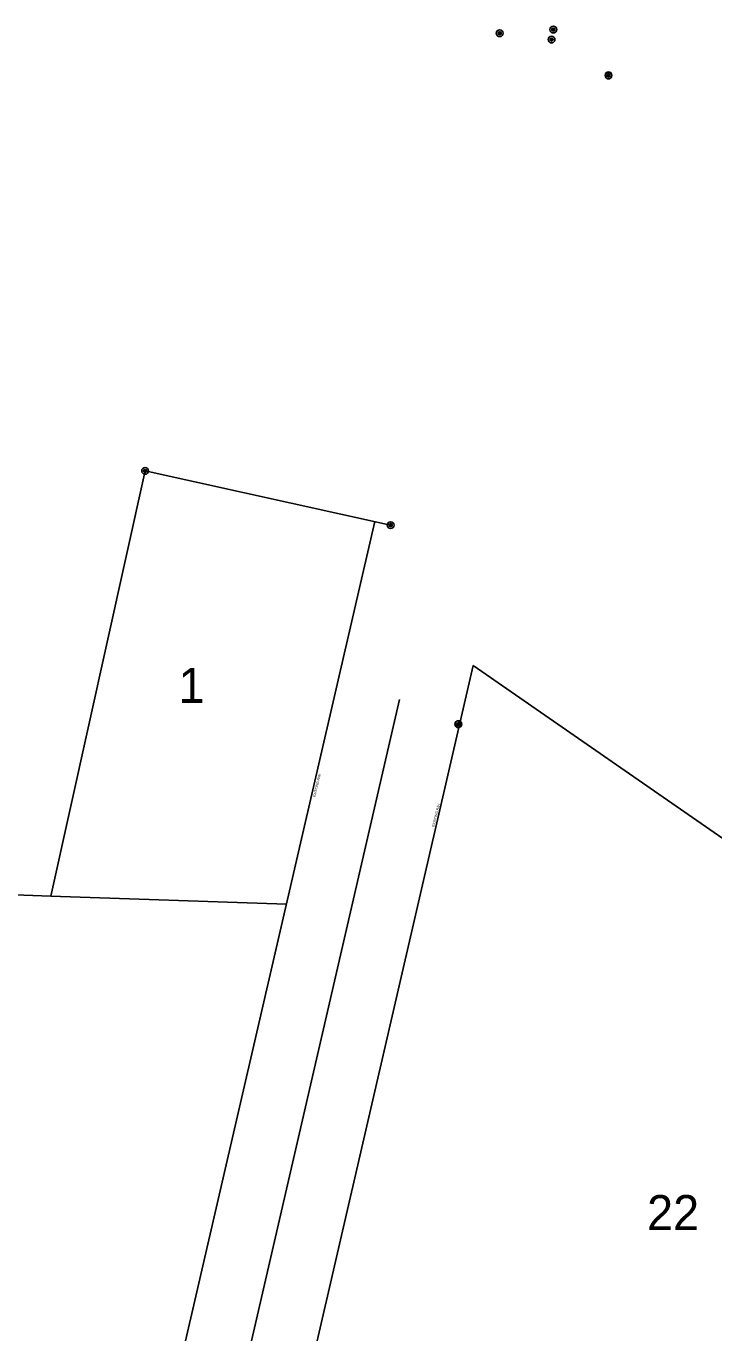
# Model space of a CAD drawing. Extents: x 1398271 to 1401121, y 1018936 to 1022764.
# Drawn here: x 1400414 to 1400768, y 1022077 to 1022749 of the extents above; entities that cross this region are included whole.
import ezdxf

# ---------------------------------------------------------------- set-up
doc = ezdxf.new("R2010")
doc.units = 0
for name, color, linetype in [('RD_EX_DV_Prop', 7, 'Continuous'), ('RD_EX_DV_PropPin', 7, 'Continuous'), ('RD_EX_DV_TX_Prop', 7, 'Continuous'), ('RD_EX_RW', 7, 'Continuous'), ('RD_EX_RW_TX', 7, 'Continuous'), ('RD_HC_Cl', 7, 'Continuous'), ('RD_SMD_Locator', 7, 'Continuous')]:
    doc.layers.add(name, color=color, linetype=linetype)

msp = doc.modelspace()

# ---------------------------------------------------------------- linework, layer by layer
at = {"layer": 'RD_EX_DV_Prop'}
for p, q in [((1400426.75, 1022301.66), (1400475.22, 1022520.32)), ((1400475.22, 1022520.32), (1400601.41, 1022492.39)), ((1400643.96, 1022420.21), (1400900.12, 1022242.43)), ((1400426.75, 1022301.66), (1400308.27, 1022305.78)), ((1400547.84, 1022297.44), (1400426.75, 1022301.66))]:
    msp.add_line(p, q, dxfattribs=at)
at = {"layer": 'RD_EX_DV_PropPin'}
for p, q in [((1400656.79, 1022745.08), (1400656.79, 1022745.47)), ((1400656.83, 1022744.97), (1400656.83, 1022745.57)), ((1400656.86, 1022744.9), (1400656.86, 1022745.64)), ((1400656.9, 1022744.85), (1400656.9, 1022745.7)), ((1400656.93, 1022744.8), (1400656.93, 1022745.75)), ((1400656.97, 1022744.76), (1400656.97, 1022745.79)), ((1400657, 1022744.72), (1400657, 1022745.82)), ((1400657.04, 1022744.69), (1400657.04, 1022745.85)), ((1400657.07, 1022744.66), (1400657.07, 1022745.88)), ((1400657.11, 1022744.64), (1400657.11, 1022745.91)), ((1400657.14, 1022744.62), (1400657.14, 1022745.93)), ((1400657.18, 1022744.6), (1400657.18, 1022745.95)), ((1400657.21, 1022744.58), (1400657.21, 1022745.97)), ((1400657.25, 1022744.56), (1400657.25, 1022745.98)), ((1400657.28, 1022744.55), (1400657.28, 1022745.99)), ((1400657.32, 1022744.54), (1400657.32, 1022746)), ((1400657.35, 1022744.53), (1400657.35, 1022746.01)), ((1400657.39, 1022744.52), (1400657.39, 1022746.02)), ((1400657.42, 1022744.52), (1400657.42, 1022746.03)), ((1400657.46, 1022744.51), (1400657.46, 1022746.03)), ((1400657.49, 1022744.51), (1400657.49, 1022746.03)), ((1400657.53, 1022744.51), (1400657.53, 1022746.03)), ((1400657.56, 1022744.51), (1400657.56, 1022746.03)), ((1400657.6, 1022744.51), (1400657.6, 1022746.03)), ((1400657.63, 1022744.52), (1400657.63, 1022746.03)), ((1400657.67, 1022744.52), (1400657.67, 1022746.02)), ((1400657.7, 1022744.53), (1400657.7, 1022746.01)), ((1400657.74, 1022744.54), (1400657.74, 1022746)), ((1400657.77, 1022744.55), (1400657.77, 1022745.99)), ((1400657.81, 1022744.56), (1400657.81, 1022745.98)), ((1400657.84, 1022744.58), (1400657.84, 1022745.97)), ((1400657.88, 1022744.6), (1400657.88, 1022745.95)), ((1400657.91, 1022744.62), (1400657.91, 1022745.93)), ((1400657.95, 1022744.64), (1400657.95, 1022745.91)), ((1400657.98, 1022744.66), (1400657.98, 1022745.88)), ((1400658.02, 1022744.69), (1400658.02, 1022745.85)), ((1400658.05, 1022744.72), (1400658.05, 1022745.82)), ((1400658.09, 1022744.76), (1400658.09, 1022745.79)), ((1400658.12, 1022744.8), (1400658.12, 1022745.75)), ((1400658.16, 1022744.85), (1400658.16, 1022745.7)), ((1400658.19, 1022744.9), (1400658.19, 1022745.64)), ((1400658.23, 1022744.97), (1400658.23, 1022745.57)), ((1400658.26, 1022745.08), (1400658.26, 1022745.47)), ((1400683.46, 1022741.82), (1400683.46, 1022742.21)), ((1400683.49, 1022741.72), (1400683.49, 1022742.31)), ((1400683.53, 1022741.64), (1400683.53, 1022742.38)), ((1400683.56, 1022741.59), (1400683.56, 1022742.44)), ((1400683.6, 1022741.54), (1400683.6, 1022742.49)), ((1400683.63, 1022741.5), (1400683.63, 1022742.53)), ((1400683.67, 1022741.46), (1400683.67, 1022742.56)), ((1400683.7, 1022741.43), (1400683.7, 1022742.6)), ((1400683.74, 1022741.4), (1400683.74, 1022742.62)), ((1400683.77, 1022741.38), (1400683.77, 1022742.65)), ((1400683.81, 1022741.36), (1400683.81, 1022742.67)), ((1400683.84, 1022741.34), (1400683.84, 1022742.69)), ((1400683.88, 1022741.32), (1400683.88, 1022742.71)), ((1400683.91, 1022741.31), (1400683.91, 1022742.72)), ((1400683.95, 1022741.29), (1400683.95, 1022742.73)), ((1400683.98, 1022741.28), (1400683.98, 1022742.74)), ((1400684.02, 1022741.27), (1400684.02, 1022742.75)), ((1400684.05, 1022741.27), (1400684.05, 1022742.76)), ((1400684.09, 1022741.26), (1400684.09, 1022742.77)), ((1400684.12, 1022741.26), (1400684.12, 1022742.77)), ((1400684.16, 1022741.25), (1400684.16, 1022742.77)), ((1400684.19, 1022741.25), (1400684.19, 1022742.77)), ((1400684.23, 1022741.25), (1400684.23, 1022742.77)), ((1400684.26, 1022741.26), (1400684.26, 1022742.77)), ((1400684.3, 1022741.26), (1400684.3, 1022742.77)), ((1400684.33, 1022741.27), (1400684.33, 1022742.76)), ((1400684.36, 1022746.98), (1400684.36, 1022747.37)), ((1400684.37, 1022741.27), (1400684.37, 1022742.75)), ((1400684.39, 1022746.87), (1400684.39, 1022747.47)), ((1400684.4, 1022741.28), (1400684.4, 1022742.74)), ((1400684.43, 1022746.8), (1400684.43, 1022747.54)), ((1400684.44, 1022741.29), (1400684.44, 1022742.73)), ((1400684.46, 1022746.74), (1400684.46, 1022747.6)), ((1400684.47, 1022741.31), (1400684.47, 1022742.72)), ((1400684.5, 1022746.7), (1400684.5, 1022747.65)), ((1400684.51, 1022741.32), (1400684.51, 1022742.71)), ((1400684.53, 1022746.66), (1400684.53, 1022747.69)), ((1400684.54, 1022741.34), (1400684.54, 1022742.69)), ((1400684.57, 1022746.62), (1400684.57, 1022747.72)), ((1400684.58, 1022741.36), (1400684.58, 1022742.67)), ((1400684.6, 1022746.59), (1400684.6, 1022747.75)), ((1400684.61, 1022741.38), (1400684.61, 1022742.65)), ((1400684.64, 1022746.56), (1400684.64, 1022747.78)), ((1400684.65, 1022741.4), (1400684.65, 1022742.62)), ((1400684.67, 1022746.54), (1400684.67, 1022747.81)), ((1400684.68, 1022741.43), (1400684.68, 1022742.6)), ((1400684.71, 1022746.52), (1400684.71, 1022747.83)), ((1400684.72, 1022741.46), (1400684.72, 1022742.56)), ((1400684.74, 1022746.5), (1400684.74, 1022747.85)), ((1400684.75, 1022741.5), (1400684.75, 1022742.53)), ((1400684.78, 1022746.48), (1400684.78, 1022747.86)), ((1400684.79, 1022741.54), (1400684.79, 1022742.49)), ((1400684.81, 1022746.46), (1400684.81, 1022747.88)), ((1400684.82, 1022741.59), (1400684.82, 1022742.44)), ((1400684.85, 1022746.45), (1400684.85, 1022747.89)), ((1400684.86, 1022741.64), (1400684.86, 1022742.38)), ((1400684.88, 1022746.44), (1400684.88, 1022747.9)), ((1400684.89, 1022741.72), (1400684.89, 1022742.31)), ((1400684.92, 1022746.43), (1400684.92, 1022747.91)), ((1400684.93, 1022741.82), (1400684.93, 1022742.21)), ((1400684.95, 1022746.42), (1400684.95, 1022747.92)), ((1400684.99, 1022746.42), (1400684.99, 1022747.93)), ((1400685.02, 1022746.41), (1400685.02, 1022747.93)), ((1400685.06, 1022746.41), (1400685.06, 1022747.93)), ((1400685.09, 1022746.41), (1400685.09, 1022747.93)), ((1400685.13, 1022746.41), (1400685.13, 1022747.93)), ((1400685.16, 1022746.41), (1400685.16, 1022747.93)), ((1400685.2, 1022746.42), (1400685.2, 1022747.93)), ((1400685.23, 1022746.42), (1400685.23, 1022747.92)), ((1400685.27, 1022746.43), (1400685.27, 1022747.91)), ((1400685.3, 1022746.44), (1400685.3, 1022747.9)), ((1400685.34, 1022746.45), (1400685.34, 1022747.89)), ((1400685.37, 1022746.46), (1400685.37, 1022747.88)), ((1400685.41, 1022746.48), (1400685.41, 1022747.86)), ((1400685.44, 1022746.5), (1400685.44, 1022747.85)), ((1400685.48, 1022746.52), (1400685.48, 1022747.83)), ((1400685.51, 1022746.54), (1400685.51, 1022747.81)), ((1400685.55, 1022746.56), (1400685.55, 1022747.78)), ((1400685.58, 1022746.59), (1400685.58, 1022747.75)), ((1400685.62, 1022746.62), (1400685.62, 1022747.72)), ((1400685.65, 1022746.66), (1400685.65, 1022747.69)), ((1400685.69, 1022746.7), (1400685.69, 1022747.65)), ((1400685.72, 1022746.74), (1400685.72, 1022747.6)), ((1400685.76, 1022746.8), (1400685.76, 1022747.54)), ((1400685.79, 1022746.87), (1400685.79, 1022747.47)), ((1400685.83, 1022746.98), (1400685.83, 1022747.37)), ((1400712.71, 1022723.31), (1400712.71, 1022723.7)), ((1400712.73, 1022723.45), (1400712.73, 1022723.85)), ((1400712.75, 1022723.21), (1400712.75, 1022723.8)), ((1400712.77, 1022723.35), (1400712.77, 1022723.95)), ((1400712.78, 1022723.14), (1400712.78, 1022723.88)), ((1400712.8, 1022723.28), (1400712.8, 1022724.02)), ((1400712.82, 1022723.08), (1400712.82, 1022723.93)), ((1400712.84, 1022723.22), (1400712.84, 1022724.08)), ((1400712.85, 1022723.03), (1400712.85, 1022723.98)), ((1400712.87, 1022723.18), (1400712.87, 1022724.12)), ((1400712.89, 1022722.99), (1400712.89, 1022724.02)), ((1400712.91, 1022723.13), (1400712.91, 1022724.16)), ((1400712.92, 1022722.96), (1400712.92, 1022724.06)), ((1400712.94, 1022723.1), (1400712.94, 1022724.2)), ((1400712.96, 1022722.92), (1400712.96, 1022724.09)), ((1400712.98, 1022723.07), (1400712.98, 1022724.23)), ((1400712.99, 1022722.9), (1400712.99, 1022724.12)), ((1400713.01, 1022723.04), (1400713.01, 1022724.26)), ((1400713.03, 1022722.87), (1400713.03, 1022724.14)), ((1400713.05, 1022723.02), (1400713.05, 1022724.28)), ((1400713.06, 1022722.85), (1400713.06, 1022724.16)), ((1400713.08, 1022722.99), (1400713.08, 1022724.31)), ((1400713.1, 1022722.83), (1400713.1, 1022724.18)), ((1400713.12, 1022722.97), (1400713.12, 1022724.33)), ((1400713.13, 1022722.81), (1400713.13, 1022724.2)), ((1400713.15, 1022722.96), (1400713.15, 1022724.34)), ((1400713.17, 1022722.8), (1400713.17, 1022724.21)), ((1400713.19, 1022722.94), (1400713.19, 1022724.36)), ((1400713.2, 1022722.79), (1400713.2, 1022724.23)), ((1400713.22, 1022722.93), (1400713.22, 1022724.37)), ((1400713.24, 1022722.78), (1400713.24, 1022724.24)), ((1400713.26, 1022722.92), (1400713.26, 1022724.38)), ((1400713.27, 1022722.77), (1400713.27, 1022724.25)), ((1400713.29, 1022722.91), (1400713.29, 1022724.39)), ((1400713.31, 1022722.76), (1400713.31, 1022724.25)), ((1400713.33, 1022722.9), (1400713.33, 1022724.4)), ((1400713.34, 1022722.75), (1400713.34, 1022724.26)), ((1400713.36, 1022722.9), (1400713.36, 1022724.4)), ((1400713.38, 1022722.75), (1400713.38, 1022724.26)), ((1400713.4, 1022722.89), (1400713.4, 1022724.41)), ((1400713.41, 1022722.75), (1400713.41, 1022724.27)), ((1400713.43, 1022722.89), (1400713.43, 1022724.41)), ((1400713.45, 1022722.75), (1400713.45, 1022724.27)), ((1400713.47, 1022722.89), (1400713.47, 1022724.41)), ((1400713.48, 1022722.75), (1400713.48, 1022724.27)), ((1400713.5, 1022722.89), (1400713.5, 1022724.41)), ((1400713.52, 1022722.75), (1400713.52, 1022724.26)), ((1400713.54, 1022722.89), (1400713.54, 1022724.41)), ((1400713.55, 1022722.75), (1400713.55, 1022724.26)), ((1400713.57, 1022722.9), (1400713.57, 1022724.4)), ((1400713.59, 1022722.76), (1400713.59, 1022724.25)), ((1400713.61, 1022722.9), (1400713.61, 1022724.4)), ((1400713.62, 1022722.77), (1400713.62, 1022724.25)), ((1400713.64, 1022722.91), (1400713.64, 1022724.39)), ((1400713.66, 1022722.78), (1400713.66, 1022724.24)), ((1400713.68, 1022722.92), (1400713.68, 1022724.38)), ((1400713.69, 1022722.79), (1400713.69, 1022724.23)), ((1400713.71, 1022722.93), (1400713.71, 1022724.37)), ((1400713.73, 1022722.8), (1400713.73, 1022724.21)), ((1400713.75, 1022722.94), (1400713.75, 1022724.36)), ((1400713.76, 1022722.81), (1400713.76, 1022724.2)), ((1400713.78, 1022722.96), (1400713.78, 1022724.34)), ((1400713.8, 1022722.83), (1400713.8, 1022724.18)), ((1400713.82, 1022722.97), (1400713.82, 1022724.33)), ((1400713.83, 1022722.85), (1400713.83, 1022724.16)), ((1400713.85, 1022722.99), (1400713.85, 1022724.31)), ((1400713.87, 1022722.87), (1400713.87, 1022724.14)), ((1400713.89, 1022723.02), (1400713.89, 1022724.28)), ((1400713.9, 1022722.9), (1400713.9, 1022724.12)), ((1400713.92, 1022723.04), (1400713.92, 1022724.26)), ((1400713.94, 1022722.92), (1400713.94, 1022724.09)), ((1400713.96, 1022723.07), (1400713.96, 1022724.23)), ((1400713.97, 1022722.96), (1400713.97, 1022724.06)), ((1400713.99, 1022723.1), (1400713.99, 1022724.2)), ((1400714.01, 1022722.99), (1400714.01, 1022724.02)), ((1400714.03, 1022723.13), (1400714.03, 1022724.16)), ((1400714.04, 1022723.03), (1400714.04, 1022723.98)), ((1400714.06, 1022723.18), (1400714.06, 1022724.12)), ((1400714.08, 1022723.08), (1400714.08, 1022723.93)), ((1400714.1, 1022723.22), (1400714.1, 1022724.08)), ((1400714.11, 1022723.14), (1400714.11, 1022723.88)), ((1400714.13, 1022723.28), (1400714.13, 1022724.02)), ((1400714.15, 1022723.21), (1400714.15, 1022723.8)), ((1400714.17, 1022723.35), (1400714.17, 1022723.95)), ((1400714.18, 1022723.31), (1400714.18, 1022723.7)), ((1400714.2, 1022723.45), (1400714.2, 1022723.85)), ((1400474.47, 1022520.08), (1400474.47, 1022520.48)), ((1400474.51, 1022519.98), (1400474.51, 1022520.58)), ((1400474.54, 1022519.91), (1400474.54, 1022520.65)), ((1400474.58, 1022519.85), (1400474.58, 1022520.71)), ((1400474.61, 1022519.81), (1400474.61, 1022520.75)), ((1400474.65, 1022519.76), (1400474.65, 1022520.8)), ((1400474.68, 1022519.73), (1400474.68, 1022520.83)), ((1400474.72, 1022519.7), (1400474.72, 1022520.86)), ((1400474.75, 1022519.67), (1400474.75, 1022520.89)), ((1400474.79, 1022519.65), (1400474.79, 1022520.91)), ((1400474.82, 1022519.62), (1400474.82, 1022520.94)), ((1400474.86, 1022519.6), (1400474.86, 1022520.96)), ((1400474.89, 1022519.59), (1400474.89, 1022520.97)), ((1400474.93, 1022519.57), (1400474.93, 1022520.99)), ((1400474.96, 1022519.56), (1400474.96, 1022521)), ((1400475, 1022519.55), (1400475, 1022521.01)), ((1400475.03, 1022519.54), (1400475.03, 1022521.02)), ((1400475.07, 1022519.53), (1400475.07, 1022521.03)), ((1400475.1, 1022519.53), (1400475.1, 1022521.03)), ((1400475.14, 1022519.52), (1400475.14, 1022521.04)), ((1400475.17, 1022519.52), (1400475.17, 1022521.04)), ((1400475.21, 1022519.52), (1400475.21, 1022521.04)), ((1400475.24, 1022519.52), (1400475.24, 1022521.04)), ((1400475.28, 1022519.52), (1400475.28, 1022521.04)), ((1400475.31, 1022519.53), (1400475.31, 1022521.03)), ((1400475.35, 1022519.53), (1400475.35, 1022521.03)), ((1400475.38, 1022519.54), (1400475.38, 1022521.02)), ((1400475.42, 1022519.55), (1400475.42, 1022521.01)), ((1400475.45, 1022519.56), (1400475.45, 1022521)), ((1400475.49, 1022519.57), (1400475.49, 1022520.99)), ((1400475.52, 1022519.59), (1400475.52, 1022520.97)), ((1400475.56, 1022519.6), (1400475.56, 1022520.96)), ((1400475.59, 1022519.62), (1400475.59, 1022520.94)), ((1400475.63, 1022519.65), (1400475.63, 1022520.91)), ((1400475.66, 1022519.67), (1400475.66, 1022520.89)), ((1400475.7, 1022519.7), (1400475.7, 1022520.86)), ((1400475.73, 1022519.73), (1400475.73, 1022520.83)), ((1400475.77, 1022519.76), (1400475.77, 1022520.8)), ((1400475.8, 1022519.81), (1400475.8, 1022520.75)), ((1400475.84, 1022519.85), (1400475.84, 1022520.71)), ((1400475.87, 1022519.91), (1400475.87, 1022520.65)), ((1400475.91, 1022519.98), (1400475.91, 1022520.58)), ((1400475.94, 1022520.08), (1400475.94, 1022520.48)), ((1400600.72, 1022492.18), (1400600.72, 1022492.58)), ((1400600.76, 1022492.08), (1400600.76, 1022492.68)), ((1400600.79, 1022492.01), (1400600.79, 1022492.75)), ((1400600.83, 1022491.95), (1400600.83, 1022492.81)), ((1400600.86, 1022491.9), (1400600.86, 1022492.85)), ((1400600.9, 1022491.86), (1400600.9, 1022492.89)), ((1400600.93, 1022491.83), (1400600.93, 1022492.93)), ((1400600.97, 1022491.8), (1400600.97, 1022492.96)), ((1400601, 1022491.77), (1400601, 1022492.99)), ((1400601.04, 1022491.74), (1400601.04, 1022493.01)), ((1400601.07, 1022491.72), (1400601.07, 1022493.04)), ((1400601.11, 1022491.7), (1400601.11, 1022493.05)), ((1400601.14, 1022491.69), (1400601.14, 1022493.07)), ((1400601.18, 1022491.67), (1400601.18, 1022493.09)), ((1400601.21, 1022491.66), (1400601.21, 1022493.1)), ((1400601.25, 1022491.65), (1400601.25, 1022493.11)), ((1400601.28, 1022491.64), (1400601.28, 1022493.12)), ((1400601.32, 1022491.63), (1400601.32, 1022493.13)), ((1400601.35, 1022491.63), (1400601.35, 1022493.13)), ((1400601.39, 1022491.62), (1400601.39, 1022493.14)), ((1400601.42, 1022491.62), (1400601.42, 1022493.14)), ((1400601.46, 1022491.62), (1400601.46, 1022493.14)), ((1400601.49, 1022491.62), (1400601.49, 1022493.14)), ((1400601.53, 1022491.62), (1400601.53, 1022493.14)), ((1400601.56, 1022491.63), (1400601.56, 1022493.13)), ((1400601.6, 1022491.63), (1400601.6, 1022493.13)), ((1400601.63, 1022491.64), (1400601.63, 1022493.12)), ((1400601.67, 1022491.65), (1400601.67, 1022493.11)), ((1400601.7, 1022491.66), (1400601.7, 1022493.1)), ((1400601.74, 1022491.67), (1400601.74, 1022493.09)), ((1400601.77, 1022491.69), (1400601.77, 1022493.07)), ((1400601.81, 1022491.7), (1400601.81, 1022493.05)), ((1400601.84, 1022491.72), (1400601.84, 1022493.04)), ((1400601.88, 1022491.74), (1400601.88, 1022493.01)), ((1400601.91, 1022491.77), (1400601.91, 1022492.99)), ((1400601.95, 1022491.8), (1400601.95, 1022492.96)), ((1400601.98, 1022491.83), (1400601.98, 1022492.93)), ((1400602.02, 1022491.86), (1400602.02, 1022492.89)), ((1400602.05, 1022491.9), (1400602.05, 1022492.85)), ((1400602.09, 1022491.95), (1400602.09, 1022492.81)), ((1400602.12, 1022492.01), (1400602.12, 1022492.75)), ((1400602.16, 1022492.08), (1400602.16, 1022492.68)), ((1400602.19, 1022492.18), (1400602.19, 1022492.58)), ((1400635.44, 1022389.85), (1400635.44, 1022390.24)), ((1400635.47, 1022389.75), (1400635.47, 1022390.34)), ((1400635.51, 1022389.67), (1400635.51, 1022390.41)), ((1400635.54, 1022389.62), (1400635.54, 1022390.47)), ((1400635.58, 1022389.57), (1400635.58, 1022390.52)), ((1400635.58, 1022389.9), (1400635.58, 1022390.29)), ((1400635.61, 1022389.53), (1400635.61, 1022390.56)), ((1400635.62, 1022389.79), (1400635.62, 1022390.39)), ((1400635.65, 1022389.49), (1400635.65, 1022390.59)), ((1400635.65, 1022389.72), (1400635.65, 1022390.46)), ((1400635.68, 1022389.46), (1400635.68, 1022390.63)), ((1400635.69, 1022389.66), (1400635.69, 1022390.52)), ((1400635.72, 1022389.43), (1400635.72, 1022390.65)), ((1400635.72, 1022389.62), (1400635.72, 1022390.57)), ((1400635.75, 1022389.41), (1400635.75, 1022390.68)), ((1400635.76, 1022389.58), (1400635.76, 1022390.61)), ((1400635.79, 1022389.39), (1400635.79, 1022390.7)), ((1400635.79, 1022389.54), (1400635.79, 1022390.64)), ((1400635.82, 1022389.37), (1400635.82, 1022390.72)), ((1400635.83, 1022389.51), (1400635.83, 1022390.67)), ((1400635.86, 1022389.35), (1400635.86, 1022390.74)), ((1400635.86, 1022389.48), (1400635.86, 1022390.7)), ((1400635.89, 1022389.34), (1400635.89, 1022390.75)), ((1400635.9, 1022389.46), (1400635.9, 1022390.73)), ((1400635.93, 1022389.32), (1400635.93, 1022390.76)), ((1400635.93, 1022389.43), (1400635.93, 1022390.75)), ((1400635.96, 1022389.31), (1400635.96, 1022390.77)), ((1400635.97, 1022389.42), (1400635.97, 1022390.77)), ((1400636, 1022389.4), (1400636, 1022390.78)), ((1400636, 1022389.3), (1400636, 1022390.78)), ((1400636.03, 1022389.3), (1400636.03, 1022390.79)), ((1400636.04, 1022389.38), (1400636.04, 1022390.8)), ((1400636.07, 1022389.37), (1400636.07, 1022390.81)), ((1400636.07, 1022389.29), (1400636.07, 1022390.8)), ((1400636.1, 1022389.29), (1400636.1, 1022390.8)), ((1400636.11, 1022389.36), (1400636.11, 1022390.82)), ((1400636.14, 1022389.35), (1400636.14, 1022390.83)), ((1400636.14, 1022389.28), (1400636.14, 1022390.8)), ((1400636.17, 1022389.28), (1400636.17, 1022390.8)), ((1400636.18, 1022389.34), (1400636.18, 1022390.84)), ((1400636.21, 1022389.34), (1400636.21, 1022390.84)), ((1400636.21, 1022389.28), (1400636.21, 1022390.8)), ((1400636.24, 1022389.29), (1400636.24, 1022390.8)), ((1400636.25, 1022389.33), (1400636.25, 1022390.85)), ((1400636.28, 1022389.33), (1400636.28, 1022390.85)), ((1400636.28, 1022389.29), (1400636.28, 1022390.8)), ((1400636.31, 1022389.3), (1400636.31, 1022390.79)), ((1400636.32, 1022389.33), (1400636.32, 1022390.85)), ((1400636.35, 1022389.33), (1400636.35, 1022390.85)), ((1400636.35, 1022389.3), (1400636.35, 1022390.78)), ((1400636.38, 1022389.31), (1400636.38, 1022390.77)), ((1400636.39, 1022389.33), (1400636.39, 1022390.85)), ((1400636.42, 1022389.34), (1400636.42, 1022390.84)), ((1400636.42, 1022389.32), (1400636.42, 1022390.76)), ((1400636.45, 1022389.34), (1400636.45, 1022390.75)), ((1400636.46, 1022389.34), (1400636.46, 1022390.84)), ((1400636.49, 1022389.35), (1400636.49, 1022390.83)), ((1400636.49, 1022389.35), (1400636.49, 1022390.74)), ((1400636.52, 1022389.37), (1400636.52, 1022390.72)), ((1400636.53, 1022389.36), (1400636.53, 1022390.82)), ((1400636.56, 1022389.37), (1400636.56, 1022390.81)), ((1400636.56, 1022389.39), (1400636.56, 1022390.7)), ((1400636.59, 1022389.41), (1400636.59, 1022390.68)), ((1400636.6, 1022389.38), (1400636.6, 1022390.8)), ((1400636.63, 1022389.4), (1400636.63, 1022390.78)), ((1400636.63, 1022389.43), (1400636.63, 1022390.65)), ((1400636.66, 1022389.46), (1400636.66, 1022390.63)), ((1400636.67, 1022389.42), (1400636.67, 1022390.77)), ((1400636.7, 1022389.43), (1400636.7, 1022390.75)), ((1400636.7, 1022389.49), (1400636.7, 1022390.59)), ((1400636.73, 1022389.53), (1400636.73, 1022390.56)), ((1400636.74, 1022389.46), (1400636.74, 1022390.73)), ((1400636.77, 1022389.48), (1400636.77, 1022390.7)), ((1400636.77, 1022389.57), (1400636.77, 1022390.52)), ((1400636.8, 1022389.62), (1400636.8, 1022390.47)), ((1400636.81, 1022389.51), (1400636.81, 1022390.67)), ((1400636.84, 1022389.54), (1400636.84, 1022390.64)), ((1400636.84, 1022389.67), (1400636.84, 1022390.41)), ((1400636.87, 1022389.75), (1400636.87, 1022390.34)), ((1400636.88, 1022389.58), (1400636.88, 1022390.61)), ((1400636.91, 1022389.62), (1400636.91, 1022390.57)), ((1400636.91, 1022389.85), (1400636.91, 1022390.24)), ((1400636.95, 1022389.66), (1400636.95, 1022390.52)), ((1400636.98, 1022389.72), (1400636.98, 1022390.46)), ((1400637.02, 1022389.79), (1400637.02, 1022390.39)), ((1400637.05, 1022389.9), (1400637.05, 1022390.29))]:
    msp.add_line(p, q, dxfattribs=at)
for centre, radius in [((1400685.09, 1022747.17), 1.75), ((1400657.53, 1022745.27), 1.75), ((1400657.53, 1022745.27), 0.761), ((1400684.19, 1022742.01), 1.75), ((1400684.19, 1022742.01), 0.761), ((1400685.09, 1022747.17), 0.761), ((1400713.45, 1022723.51), 1.75), ((1400713.47, 1022723.65), 1.75), ((1400713.45, 1022723.51), 0.761), ((1400713.47, 1022723.65), 0.761), ((1400475.21, 1022520.28), 1.75), ((1400475.21, 1022520.28), 0.761), ((1400601.46, 1022492.38), 1.75), ((1400601.46, 1022492.38), 0.761), ((1400636.17, 1022390.04), 1.75), ((1400636.32, 1022390.09), 1.75), ((1400636.17, 1022390.04), 0.761), ((1400636.32, 1022390.09), 0.761)]:
    msp.add_circle(centre, radius, dxfattribs=at)
at = {"layer": 'RD_EX_RW'}
for p, q in [((1400445.34, 1021854.1), (1400593.32, 1022494.18)), ((1400509.64, 1021839.24), (1400643.96, 1022420.21))]:
    msp.add_line(p, q, dxfattribs=at)
at = {"layer": 'RD_HC_Cl'}
msp.add_line((1400477.49, 1021846.67), (1400606.05, 1022402.73), dxfattribs=at)
at = {"layer": 'RD_SMD_Locator'}
for centre in [(1400657.53, 1022745.27), (1400684.19, 1022742.01), (1400685.09, 1022747.17), (1400713.45, 1022723.51), (1400713.47, 1022723.65), (1400475.21, 1022520.28), (1400601.46, 1022492.38), (1400636.17, 1022390.04), (1400636.32, 1022390.09)]:
    msp.add_circle(centre, 0.15, dxfattribs=at)

# ---------------------------------------------------------------- texts
at = {"layer": 'RD_EX_DV_TX_Prop'}
for s, p in [('1', (1400492.4, 1022401)), ('22', (1400733.28, 1022129.98))]:
    msp.add_text(s, height=18, dxfattribs=at).set_placement(p)
at = {"layer": 'RD_EX_RW_TX'}
for p in [(1400562.7, 1022352.48), (1400623.91, 1022337.17)]:
    msp.add_text('EXISTING R/W', height=1.28, rotation=75.98157, dxfattribs=at).set_placement(p)

doc.saveas('drawing.dxf')
